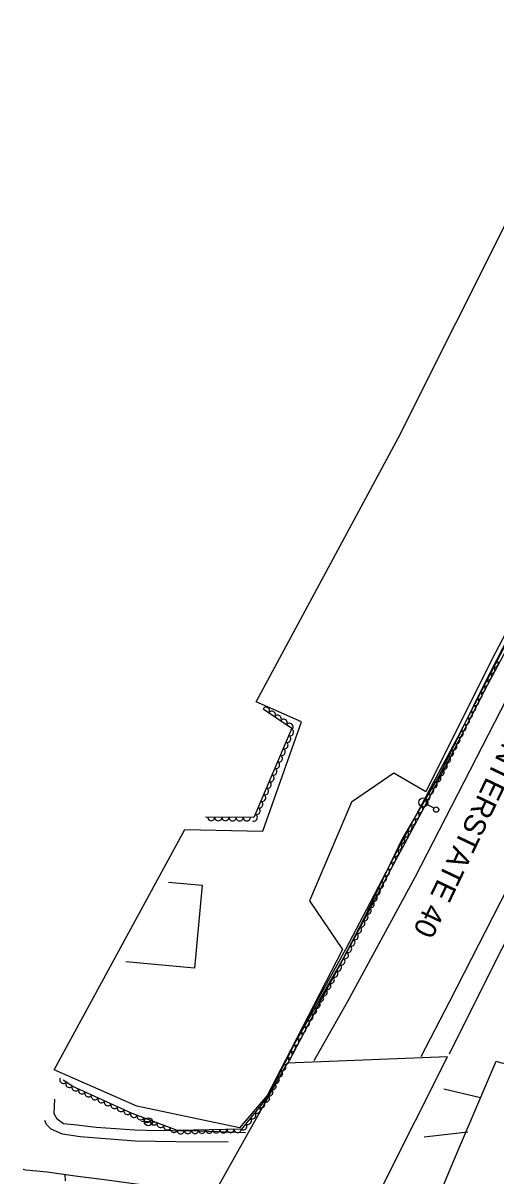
# Model space of a CAD drawing. Extents: x 1722896 to 1754269, y 648279 to 666297.
# Drawn here: x 1725736 to 1726002, y 665650 to 666297 of the extents above; entities that cross this region are included whole.
import ezdxf

# ---------------------------------------------------------------- set-up
doc = ezdxf.new("R2010")
doc.units = 0
for name, color, linetype in [('DESIGN - CENTERLINE - Proposed', 7, 'Continuous'), ('DESIGN - CENTERLINE - Proposed Text', 7, 'Continuous'), ('DESIGN - SCRATCH - User 1', 7, 'Continuous'), ('DESIGN - SHEET - Linework', 7, 'Continuous'), ('SURVEY - CENTERLINE - Preliminary', 7, 'Continuous'), ('SURVEY - CENTERLINE - Preliminary Text', 7, 'Continuous'), ('SURVEY - DTM - Breaklines', 7, 'Continuous'), ('SURVEY - VEGETATION - Features with Text', 7, 'Continuous')]:
    doc.layers.add(name, color=color, linetype=linetype)

msp = doc.modelspace()

# ---------------------------------------------------------------- linework, layer by layer
at = {"layer": 'DESIGN - CENTERLINE - Proposed'}
for points in [[(1725938.34, 665644.83), (1725974.38, 665716.5), (1725884.42, 665712.96), (1725826.95, 665610.59)], [(1725977.36, 665657.03), (1726001.65, 665714.13), (1726004.81, 665713.24), (1726074.76, 665703.7), (1726077.99, 665703.46), (1726071.21, 665685.6)], [(1725960.31, 665615.78), (1725977.36, 665657.03)]]:
    msp.add_lwpolyline(points, dxfattribs=at)
at = {"layer": 'DESIGN - CENTERLINE - Proposed Text'}
msp.add_lwpolyline([(1725817.83, 665814.65), (1725836.78, 665812.92), (1725832.54, 665766.37), (1725793.96, 665769.88)], dxfattribs=at)
at = {"layer": 'DESIGN - SCRATCH - User 1'}
for points in [[(1725883.56, 665714.53), (1725900.67, 665746.94), (1725917.36, 665777.04), (1725931.18, 665803.31), (1725946.97, 665833.49), (1725965.25, 665868.17), (1725980.22, 665896.05), (1725996.27, 665927.26), (1726012.08, 665957.42), (1726027.88, 665987.99), (1726043.63, 666020.12), (1726058.6, 666050.26), (1726072.81, 666080.93), (1726089.38, 666116.54), (1726106.29, 666152.02), (1726119.61, 666180.7), (1726133.9, 666210.49), (1726148.45, 666241.52), (1726162.75, 666271.37)], [(1726164.02, 666270.93), (1726164.1, 666270.91), (1726154.69, 666251.41), (1726144.81, 666230.97), (1726134.69, 666208.87), (1726119.39, 666176.13), (1726110.05, 666156.17), (1726094.55, 666124.21), (1726080.52, 666093.87), (1726063.12, 666056.57), (1726047.46, 666024.21), (1726028.85, 665986.55), (1726011.41, 665952.74), (1725995.45, 665922.56), (1725980.72, 665894.19), (1725962.44, 665858.67), (1725944.03, 665824.25), (1725926.59, 665791.37), (1725903.76, 665748.94), (1725885.5, 665714.32)], [(1726147.6, 666062.13), (1726145.65, 666059.78), (1726124.34, 666015.55), (1726098.62, 665964.01), (1726073.03, 665911.1), (1726048.21, 665862.22), (1726021.75, 665810.59), (1725987.72, 665743.04), (1725975.37, 665718.07)]]:
    msp.add_lwpolyline(points, dxfattribs=at)
at = {"layer": 'SURVEY - CENTERLINE - Preliminary'}
for points in [[(1725883.45, 665714.66), (1725873.26, 665694.89), (1725857.67, 665676.84), (1725800.05, 665688.95), (1725753.69, 665709.28), (1725827.03, 665844.09), (1725870.83, 665843.31), (1725892.58, 665904.51), (1725867.01, 665915.72), (1725946.92, 666064.16), (1726011.72, 666193.28), (1726078.11, 666294.1), (1726120.84, 666296.69), (1726172.83, 666284.28)], [(1726163.93, 666271.12), (1726148.28, 666248.01), (1726068.35, 666079.3), (1726042.5, 666021.89), (1725999.33, 665939.48), (1725962.2, 665865.36), (1725944.36, 665875.69), (1725920.63, 665859.54), (1725897, 665804.15), (1725915.53, 665776.91), (1725883.47, 665714.69)]]:
    msp.add_lwpolyline(points, dxfattribs=at)
at = {"layer": 'SURVEY - CENTERLINE - Preliminary Text'}
for points in [[(1726169.69, 666254.61), (1726143.63, 666196.79), (1726111.12, 666128.78), (1726059.94, 666021.58), (1726004.19, 665910.82), (1725956.15, 665817.3), (1725918.15, 665747.27)], [(1726212.66, 666233.87), (1726181.61, 666166.13), (1726144.69, 666088.52), (1726109.49, 666016.58), (1726085.79, 665966.87), (1726053.61, 665902.62), (1726012.25, 665819.21), (1725975.45, 665747.31)], [(1725918.15, 665747.27), (1725899.5, 665714.26)], [(1725975.45, 665747.31), (1725959.49, 665716.5)], [(1725861.01, 665673.86), (1725835.08, 665674.84), (1725805.34, 665675.18), (1725799.04, 665675.51), (1725777.25, 665676.88), (1725766.42, 665678.22), (1725759.03, 665679.06), (1725755.35, 665681.58), (1725753.72, 665684.67), (1725754.17, 665692.77)], [(1725851.35, 665668.75), (1725821.99, 665668.89), (1725799.1, 665669.19), (1725768.35, 665671.79), (1725758.32, 665673.22), (1725751.98, 665675.95), (1725749.48, 665678.54), (1725748.57, 665680.88)], [(1725842.2, 665636.1), (1725802.48, 665644.68), (1725781.92, 665647.53), (1725765.57, 665649.6), (1725749.82, 665651.78), (1725737.77, 665652.96), (1725736.27, 665653.36)]]:
    msp.add_lwpolyline(points, dxfattribs=at)
at = {"layer": 'SURVEY - DTM - Breaklines'}
for p, q in [((1725960.89, 665859.38), (1725962.73, 665862.64)), ((1725960.89, 665859.38), (1725959.05, 665856.11)), ((1725966.78, 665856.06), (1725963.07, 665858.15)), ((1725806.57, 665680.15), (1725802.82, 665680.29)), ((1725806.57, 665680.15), (1725810.32, 665680.01)), ((1725760, 665646.96), (1725759.87, 665650.71))]:
    msp.add_line(p, q, dxfattribs=at)
for centre, radius in [((1725960.89, 665859.38), 2.5), ((1725968.08, 665855.33), 1.5), ((1725806.57, 665680.15), 2.25)]:
    msp.add_circle(centre, radius, dxfattribs=at)
at = {"layer": 'SURVEY - VEGETATION - Features with Text'}
for points in [[(1726165.31, 666268.38), (1726152.25, 666249.2), (1726132.96, 666210.67), (1726113.81, 666167.99), (1726088.69, 666116.56), (1726059.21, 666054.01), (1726035.59, 666003.82), (1726015.62, 665965.66), (1725995.03, 665925.63), (1725970.03, 665874.92), (1725948.85, 665838.58), (1725927.55, 665794.1), (1725915.96, 665771.73), (1725888.7, 665724.31), (1725873.18, 665693.81), (1725858.78, 665676.03), (1725822.9, 665675.22), (1725797.45, 665684.88), (1725764.14, 665700), (1725758.83, 665703.58)], [(1725870.99, 665911.96), (1725887.14, 665900.97), (1725865.84, 665850.84), (1725838.59, 665851.01)], [(1725972.4, 665698.61), (1725992.96, 665693.74)], [(1725985.88, 665674.29), (1725961.37, 665671.6)]]:
    msp.add_lwpolyline(points, dxfattribs=at)
for centre, major_axis in [((1726000.98, 665937.2), (-0.91, -1.78)), ((1725997.32, 665930.08), (-0.91, -1.78)), ((1725999.15, 665933.64), (-0.91, -1.78)), ((1725993.71, 665922.95), (-0.88, -1.79)), ((1725995.5, 665926.53), (-0.91, -1.78)), ((1725991.94, 665919.36), (-0.88, -1.79)), ((1725872.64, 665910.84), (1.65, -1.13)), ((1725988.4, 665912.18), (-0.88, -1.79)), ((1725990.17, 665915.77), (-0.88, -1.79)), ((1725875.95, 665908.59), (1.65, -1.13)), ((1725879.25, 665906.34), (1.65, -1.13)), ((1725882.56, 665904.09), (1.65, -1.13)), ((1725984.87, 665905.01), (-0.88, -1.79)), ((1725986.64, 665908.6), (-0.88, -1.79)), ((1725885.87, 665901.83), (1.65, -1.13)), ((1725886.18, 665898.7), (-0.78, -1.84)), ((1725981.33, 665897.83), (-0.88, -1.79)), ((1725983.1, 665901.42), (-0.88, -1.79)), ((1725883.05, 665891.34), (-0.78, -1.84)), ((1725884.61, 665895.02), (-0.78, -1.84)), ((1725977.79, 665890.66), (-0.88, -1.79)), ((1725979.56, 665894.25), (-0.88, -1.79)), ((1725881.48, 665887.66), (-0.78, -1.84)), ((1725976.02, 665887.07), (-0.88, -1.79)), ((1725878.35, 665880.3), (-0.78, -1.84)), ((1725879.92, 665883.98), (-0.78, -1.84)), ((1725972.48, 665879.9), (-0.88, -1.79)), ((1725974.25, 665883.48), (-0.88, -1.79)), ((1725875.23, 665872.94), (-0.78, -1.84)), ((1725876.79, 665876.62), (-0.78, -1.84)), ((1725968.8, 665872.8), (-1.01, -1.73)), ((1725970.72, 665876.31), (-0.88, -1.79)), ((1725872.1, 665865.57), (-0.78, -1.84)), ((1725873.66, 665869.25), (-0.78, -1.84)), ((1725964.77, 665865.89), (-1.01, -1.73)), ((1725966.78, 665869.35), (-1.01, -1.73)), ((1725868.97, 665858.21), (-0.78, -1.84)), ((1725870.53, 665861.89), (-0.78, -1.84)), ((1725960.74, 665858.98), (-1.01, -1.73)), ((1725962.75, 665862.43), (-1.01, -1.73)), ((1725867.4, 665854.53), (-0.78, -1.84)), ((1725956.71, 665852.07), (-1.01, -1.73)), ((1725958.73, 665855.52), (-1.01, -1.73)), ((1725841.84, 665850.99), (-2, 0.01)), ((1725845.84, 665850.97), (-2, 0.01)), ((1725849.84, 665850.94), (-2, 0.01)), ((1725853.84, 665850.92), (-2, 0.01)), ((1725857.84, 665850.89), (-2, 0.01)), ((1725861.84, 665850.87), (-2, 0.01)), ((1725865.84, 665850.85), (-0.78, -1.84)), ((1725954.7, 665848.61), (-1.01, -1.73)), ((1725950.67, 665841.7), (-1.01, -1.73)), ((1725952.68, 665845.15), (-1.01, -1.73)), ((1725946.96, 665834.62), (-0.86, -1.8)), ((1725948.68, 665838.23), (-0.86, -1.8)), ((1725943.5, 665827.4), (-0.86, -1.8)), ((1725945.23, 665831.01), (-0.86, -1.8)), ((1725940.05, 665820.19), (-0.86, -1.8)), ((1725941.77, 665823.8), (-0.86, -1.8)), ((1725936.59, 665812.97), (-0.86, -1.8)), ((1725938.32, 665816.58), (-0.86, -1.8)), ((1725934.86, 665809.37), (-0.86, -1.8)), ((1725931.41, 665802.15), (-0.86, -1.8)), ((1725933.13, 665805.76), (-0.86, -1.8)), ((1725927.95, 665794.94), (-0.86, -1.8)), ((1725929.68, 665798.54), (-0.86, -1.8)), ((1725924.3, 665787.82), (-0.92, -1.78)), ((1725926.14, 665791.37), (-0.92, -1.78)), ((1725920.62, 665780.72), (-0.92, -1.78)), ((1725922.46, 665784.27), (-0.92, -1.78)), ((1725918.78, 665777.16), (-0.92, -1.78)), ((1725915.02, 665770.1), (-1, -1.73)), ((1725916.94, 665773.61), (-0.92, -1.78)), ((1725911.04, 665763.17), (-1, -1.73)), ((1725913.03, 665766.63), (-1, -1.73)), ((1725907.05, 665756.23), (-1, -1.73)), ((1725909.04, 665759.7), (-1, -1.73)), ((1725903.06, 665749.29), (-1, -1.73)), ((1725905.06, 665752.76), (-1, -1.73)), ((1725899.08, 665742.36), (-1, -1.73)), ((1725901.07, 665745.83), (-1, -1.73)), ((1725895.09, 665735.42), (-1, -1.73)), ((1725897.08, 665738.89), (-1, -1.73)), ((1725893.1, 665731.95), (-1, -1.73)), ((1725889.11, 665725.02), (-1, -1.73)), ((1725891.1, 665728.49), (-1, -1.73)), ((1725885.44, 665717.91), (-0.91, -1.78)), ((1725887.26, 665721.47), (-0.91, -1.78)), ((1725881.82, 665710.78), (-0.91, -1.78)), ((1725883.63, 665714.34), (-0.91, -1.78)), ((1725878.19, 665703.65), (-0.91, -1.78)), ((1725880, 665707.21), (-0.91, -1.78)), ((1725758.85, 665703.57), (-1.66, 1.12)), ((1725762.16, 665701.33), (-1.66, 1.12)), ((1725765.61, 665699.33), (-1.82, 0.83)), ((1725769.25, 665697.68), (-1.82, 0.83)), ((1725874.56, 665696.52), (-0.91, -1.78)), ((1725876.37, 665700.08), (-0.91, -1.78)), ((1725772.9, 665696.03), (-1.82, 0.83)), ((1725776.54, 665694.37), (-1.82, 0.83)), ((1725780.18, 665692.72), (-1.82, 0.83)), ((1725783.82, 665691.07), (-1.82, 0.83)), ((1725872.58, 665693.06), (-1.26, -1.55)), ((1725787.46, 665689.41), (-1.82, 0.83)), ((1725791.11, 665687.76), (-1.82, 0.83)), ((1725794.75, 665686.11), (-1.82, 0.83)), ((1725867.54, 665686.85), (-1.26, -1.55)), ((1725870.06, 665689.95), (-1.26, -1.55)), ((1725798.42, 665684.51), (-1.87, 0.71)), ((1725802.16, 665683.09), (-1.87, 0.71)), ((1725805.9, 665681.68), (-1.87, 0.71)), ((1725809.64, 665680.26), (-1.87, 0.71)), ((1725813.38, 665678.84), (-1.87, 0.71)), ((1725859.99, 665677.52), (-1.26, -1.55)), ((1725862.51, 665680.63), (-1.26, -1.55)), ((1725865.03, 665683.74), (-1.26, -1.55)), ((1725817.12, 665677.42), (-1.87, 0.71)), ((1725820.85, 665676), (-1.87, 0.71)), ((1725824.71, 665675.26), (-2, -0.04)), ((1725828.71, 665675.35), (-2, -0.04)), ((1725832.71, 665675.44), (-2, -0.04)), ((1725836.71, 665675.53), (-2, -0.04)), ((1725840.71, 665675.62), (-2, -0.04)), ((1725844.71, 665675.71), (-2, -0.04)), ((1725848.71, 665675.8), (-2, -0.04)), ((1725852.71, 665675.89), (-2, -0.04)), ((1725856.7, 665675.98), (-2, -0.04))]:
    msp.add_ellipse(centre, major_axis=major_axis, ratio=0.940188, start_param=0, end_param=3.141593, dxfattribs=at)

# ---------------------------------------------------------------- texts
at = {"layer": 'DESIGN - SHEET - Linework'}
msp.add_text('INTERSTATE 40', height=12, rotation=244.45437, dxfattribs=at).set_placement((1726007.56, 665897.47))

doc.saveas('drawing.dxf')
